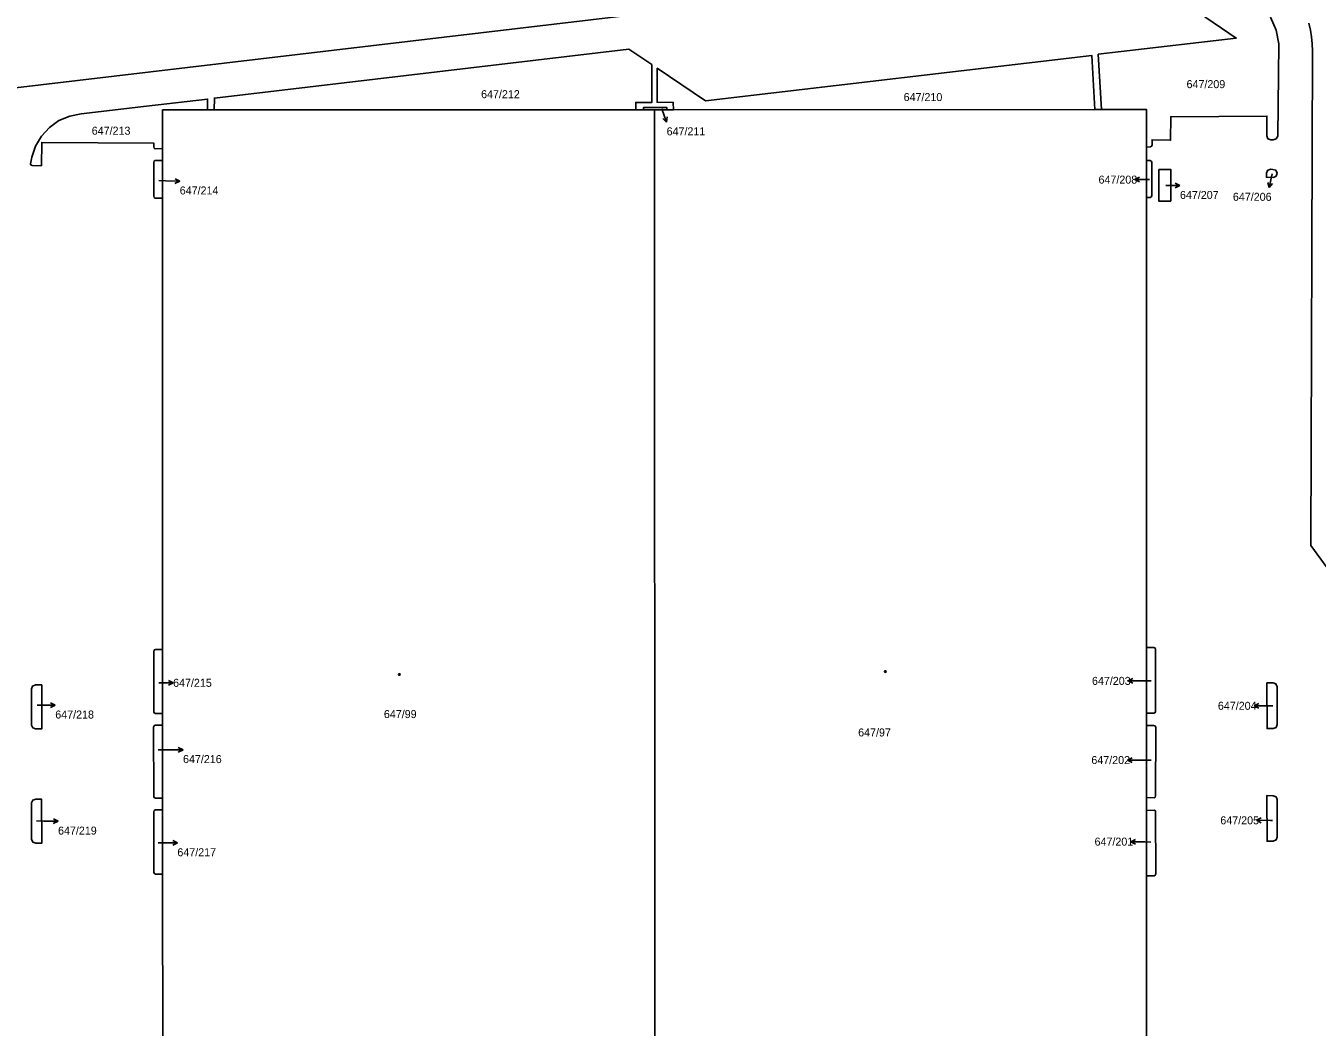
# Model space of a CAD drawing. Extents: x -724107 to -720612, y -1045267 to -1038441.
# Drawn here: x -722891.5 to -722617.2, y -1041657.4 to -1041444.7 of the extents above; entities that cross this region are included whole.
import ezdxf

# ---------------------------------------------------------------- set-up
doc = ezdxf.new("R2010")
doc.units = 0
for name, color, linetype in [('Hranice parcel', 7, 'Continuous'), ('Parcelní čísla', 7, 'Continuous'), ('Pop  PČ popisy', 7, 'Continuous'), ('Značky budov', 7, 'Continuous')]:
    doc.layers.add(name, color=color, linetype=linetype)

msp = doc.modelspace()

# ---------------------------------------------------------------- linework, layer by layer
at = {"layer": 'Hranice parcel'}
for p, q in [((-722851.47, -1041462.53), (-722852.91, -1041462.53)), ((-722761.96, -1041462.5), (-722851.47, -1041462.53)), ((-722760.31, -1041462.5), (-722761.96, -1041462.5)), ((-722757.93, -1041462.5), (-722760.31, -1041462.5)), ((-722757.93, -1041462.5), (-722757.91, -1041757.48)), ((-722755.37, -1041462.5), (-722757.93, -1041462.5)), ((-722753.96, -1041462.5), (-722755.37, -1041462.5)), ((-722664.39, -1041462.46), (-722753.96, -1041462.5)), ((-722663, -1041462.46), (-722664.39, -1041462.46)), ((-722862.46, -1041470.71), (-722862.46, -1041473.28)), ((-722653.43, -1041473.31), (-722653.43, -1041470.44)), ((-722862.46, -1041473.28), (-722862.46, -1041481.25)), ((-722653.43, -1041481.14), (-722653.43, -1041473.31)), ((-722862.46, -1041481.25), (-722862.45, -1041577.13)), ((-722653.42, -1041576.75), (-722653.43, -1041481.14)), ((-722862.45, -1041577.13), (-722862.45, -1041590.75)), ((-722653.42, -1041590.7), (-722653.42, -1041576.75)), ((-722862.45, -1041590.75), (-722862.45, -1041593.25)), ((-722653.42, -1041593.34), (-722653.42, -1041590.7)), ((-722862.45, -1041593.25), (-722862.45, -1041608.73)), ((-722653.42, -1041608.63), (-722653.42, -1041593.34)), ((-722862.45, -1041608.73), (-722862.45, -1041611.24)), ((-722653.42, -1041611.36), (-722653.42, -1041608.63)), ((-722862.45, -1041611.24), (-722862.45, -1041624.86)), ((-722653.42, -1041625.24), (-722653.42, -1041611.36)), ((-722862.45, -1041624.86), (-722862.43, -1041739.13)), ((-722653.41, -1041739.26), (-722653.42, -1041625.24))]:
    msp.add_line(p, q, dxfattribs=at)
for points in [[(-723065.73, -1041477.97), (-722911.77, -1041459.96), (-722763.68, -1041442.46), (-722640.12, -1041427.88)], [(-722663, -1041462.46), (-722663.7, -1041450.72), (-722634.39, -1041447.26), (-722650.43, -1041436.3)], [(-722627.08, -1041442.84), (-722625.91, -1041445.59), (-722625.34, -1041448.51), (-722625.58, -1041468.11), (-722625.92, -1041468.69), (-722626.54, -1041468.9), (-722627.05, -1041468.9), (-722627.67, -1041468.67), (-722627.9, -1041468.07), (-722627.87, -1041463.84), (-722648.31, -1041463.98), (-722648.32, -1041468.98), (-722652.26, -1041468.87), (-722652.26, -1041469.99), (-722652.37, -1041470.25), (-722652.59, -1041470.37), (-722653.43, -1041470.44)], [(-722618.95, -1041444.12), (-722618.61, -1041445.57), (-722618.36, -1041447.03), (-722618.22, -1041448.51), (-722618.18, -1041449.99)], [(-722851.47, -1041462.53), (-722851.46, -1041460.03), (-722763.39, -1041449.65), (-722758.54, -1041452.91), (-722758.52, -1041460.95), (-722761.93, -1041460.94), (-722761.96, -1041462.5)], [(-722753.96, -1041462.5), (-722753.98, -1041460.93), (-722757.41, -1041460.91), (-722757.39, -1041453.69), (-722747.11, -1041460.6), (-722665.06, -1041450.95), (-722664.39, -1041462.46)], [(-722618.18, -1041449.99), (-722618.53, -1041555.06), (-722615.08, -1041559.79), (-722614.93, -1041733.5), (-722618.38, -1041738.26), (-722618.4, -1041745.25)], [(-722862.46, -1041470.71), (-722864.02, -1041470.77), (-722864.25, -1041470.63), (-722864.33, -1041470.37), (-722864.34, -1041469.59), (-722888.12, -1041469.44), (-722888.21, -1041474.39), (-722890.18, -1041474.36), (-722890.42, -1041474.23), (-722890.52, -1041474.01), (-722890.22, -1041472.59), (-722889.47, -1041470.23), (-722888.21, -1041468.1), (-722886.5, -1041466.26), (-722884.48, -1041464.81), (-722882.17, -1041463.86), (-722879.75, -1041463.38), (-722865.85, -1041461.76), (-722852.92, -1041460.23), (-722852.91, -1041462.53)], [(-722852.91, -1041462.53), (-722862.46, -1041462.53), (-722862.46, -1041470.71)], [(-722760.31, -1041462.5), (-722760.33, -1041462.05), (-722755.37, -1041462.01), (-722755.37, -1041462.5)], [(-722653.43, -1041470.44), (-722653.43, -1041462.46), (-722663, -1041462.46)], [(-722862.46, -1041481.25), (-722864.01, -1041481.28), (-722864.27, -1041481.12), (-722864.34, -1041480.88), (-722864.34, -1041473.68), (-722864.26, -1041473.41), (-722864.01, -1041473.29), (-722862.46, -1041473.28)], [(-722653.43, -1041473.31), (-722652.68, -1041473.3), (-722652.44, -1041473.4), (-722652.32, -1041473.65), (-722652.31, -1041480.79), (-722652.43, -1041481.01), (-722652.69, -1041481.12), (-722653.43, -1041481.14)], [(-722650.82, -1041475.19), (-722648.31, -1041475.18), (-722648.29, -1041481.9), (-722650.85, -1041481.89), (-722650.82, -1041475.19)], [(-722625.68, -1041475.96), (-722625.93, -1041476.58), (-722626.49, -1041476.87), (-722627.96, -1041476.84), (-722627.93, -1041475.98), (-722627.71, -1041475.38), (-722627.1, -1041475.15), (-722626.61, -1041475.16), (-722625.95, -1041475.34), (-722625.68, -1041475.96)], [(-722862.45, -1041590.75), (-722863.99, -1041590.74), (-722864.22, -1041590.65), (-722864.34, -1041590.4), (-722864.32, -1041577.49), (-722864.2, -1041577.25), (-722863.96, -1041577.14), (-722862.45, -1041577.13)], [(-722653.42, -1041576.75), (-722651.86, -1041576.73), (-722651.65, -1041576.82), (-722651.52, -1041577.1), (-722651.52, -1041590.32), (-722651.61, -1041590.56), (-722651.86, -1041590.69), (-722653.42, -1041590.7)], [(-722890.05, -1041593.8), (-722890.34, -1041593.22), (-722890.29, -1041585.55), (-722890.07, -1041584.95), (-722889.46, -1041584.67), (-722888.14, -1041584.69), (-722888.14, -1041594.03), (-722889.44, -1041594.02), (-722890.05, -1041593.8)], [(-722627.86, -1041584.22), (-722626.55, -1041584.23), (-722625.94, -1041584.47), (-722625.68, -1041585.08), (-722625.68, -1041593.1), (-722625.93, -1041593.71), (-722626.53, -1041593.96), (-722627.82, -1041593.98), (-722627.86, -1041584.22)], [(-722862.45, -1041608.73), (-722863.99, -1041608.77), (-722864.26, -1041608.63), (-722864.35, -1041608.39), (-722864.36, -1041593.63), (-722864.27, -1041593.37), (-722864.01, -1041593.25), (-722862.45, -1041593.25)], [(-722653.42, -1041593.34), (-722651.86, -1041593.34), (-722651.63, -1041593.41), (-722651.49, -1041593.71), (-722651.53, -1041608.27), (-722651.63, -1041608.54), (-722651.85, -1041608.65), (-722653.42, -1041608.63)], [(-722625.66, -1041609.05), (-722625.68, -1041617.05), (-722625.89, -1041617.63), (-722626.52, -1041617.87), (-722627.84, -1041617.89), (-722627.85, -1041608.16), (-722626.54, -1041608.22), (-722625.91, -1041608.43), (-722625.66, -1041609.05)], [(-722890.32, -1041609.75), (-722890.01, -1041609.15), (-722889.41, -1041608.95), (-722888.17, -1041608.96), (-722888.11, -1041618.29), (-722889.39, -1041618.3), (-722890.02, -1041618.11), (-722890.28, -1041617.47), (-722890.32, -1041609.75)], [(-722862.45, -1041624.86), (-722863.98, -1041624.87), (-722864.21, -1041624.77), (-722864.33, -1041624.51), (-722864.35, -1041611.62), (-722864.26, -1041611.4), (-722864, -1041611.26), (-722862.45, -1041611.24)], [(-722653.42, -1041611.36), (-722651.83, -1041611.28), (-722651.57, -1041611.46), (-722651.5, -1041611.7), (-722651.49, -1041624.85), (-722651.59, -1041625.13), (-722651.84, -1041625.22), (-722653.42, -1041625.24)]]:
    msp.add_lwpolyline(points, dxfattribs=at)
at = {"layer": 'Pop  PČ popisy'}
for p, q in [((-722756.43, -1041462.29), (-722755.4, -1041465.11)), ((-722755.4, -1041465.11), (-722756.22, -1041464.34)), ((-722755.4, -1041465.11), (-722755.28, -1041464)), ((-722626.73, -1041476.09), (-722627.41, -1041479.01)), ((-722863.26, -1041477.53), (-722861.82, -1041477.57)), ((-722861.82, -1041477.57), (-722858.82, -1041477.68)), ((-722858.82, -1041477.68), (-722859.84, -1041478.14)), ((-722858.82, -1041477.68), (-722859.8, -1041477.14)), ((-722655.96, -1041477.34), (-722654.96, -1041476.84)), ((-722652.96, -1041477.34), (-722655.96, -1041477.34)), ((-722655.96, -1041477.34), (-722654.96, -1041477.84)), ((-722652.96, -1041477.34), (-722652.84, -1041477.34)), ((-722649.34, -1041478.62), (-722646.34, -1041478.62)), ((-722646.34, -1041478.62), (-722647.34, -1041478.12)), ((-722646.34, -1041478.62), (-722647.34, -1041479.12)), ((-722627.41, -1041479.01), (-722627.67, -1041477.93)), ((-722627.41, -1041479.01), (-722626.69, -1041478.15)), ((-722657.35, -1041583.83), (-722656.35, -1041583.33)), ((-722863.23, -1041584.28), (-722860.23, -1041584.23)), ((-722860.23, -1041584.23), (-722861.24, -1041583.74)), ((-722860.23, -1041584.23), (-722861.22, -1041584.75)), ((-722654.35, -1041583.83), (-722657.35, -1041583.83)), ((-722657.35, -1041583.83), (-722656.35, -1041584.33)), ((-722654.35, -1041583.83), (-722652.49, -1041583.83)), ((-722885.26, -1041589), (-722886.26, -1041588.5)), ((-722630.6, -1041589.12), (-722629.6, -1041588.62)), ((-722888.26, -1041589), (-722889.1, -1041589)), ((-722888.26, -1041589), (-722885.26, -1041589)), ((-722885.26, -1041589), (-722886.26, -1041589.5)), ((-722627.6, -1041589.12), (-722630.6, -1041589.12)), ((-722630.6, -1041589.12), (-722629.6, -1041589.62)), ((-722627.6, -1041589.12), (-722626.58, -1041589.12)), ((-722861.12, -1041598.46), (-722863.41, -1041598.46)), ((-722861.12, -1041598.46), (-722858.12, -1041598.46)), ((-722858.12, -1041598.46), (-722859.12, -1041597.96)), ((-722858.12, -1041598.46), (-722859.12, -1041598.96)), ((-722657.48, -1041600.65), (-722656.48, -1041600.15)), ((-722654.48, -1041600.65), (-722657.48, -1041600.65)), ((-722657.48, -1041600.65), (-722656.48, -1041601.15)), ((-722654.48, -1041600.65), (-722652.45, -1041600.65)), ((-722889.28, -1041613.58), (-722887.67, -1041613.61)), ((-722887.67, -1041613.61), (-722884.67, -1041613.66)), ((-722884.67, -1041613.66), (-722885.68, -1041614.15)), ((-722884.67, -1041613.66), (-722885.66, -1041613.14)), ((-722630.08, -1041613.44), (-722629.07, -1041612.95)), ((-722627.08, -1041613.49), (-722630.08, -1041613.44)), ((-722630.08, -1041613.44), (-722629.09, -1041613.96)), ((-722627.08, -1041613.49), (-722626.67, -1041613.49)), ((-722862.32, -1041618.26), (-722863.41, -1041618.26)), ((-722862.32, -1041618.26), (-722859.32, -1041618.26)), ((-722859.32, -1041618.26), (-722860.32, -1041617.76)), ((-722859.32, -1041618.26), (-722860.32, -1041618.76)), ((-722656.8, -1041617.99), (-722655.79, -1041617.5)), ((-722653.8, -1041618.04), (-722656.8, -1041617.99)), ((-722656.8, -1041617.99), (-722655.81, -1041618.51)), ((-722652.53, -1041618.06), (-722653.8, -1041618.04))]:
    msp.add_line(p, q, dxfattribs=at)
at = {"layer": 'Značky budov'}
for centre in [(-722812.18, -1041582.46), (-722708.94, -1041581.85)]:
    msp.add_circle(centre, 0.175, dxfattribs=at)

# ---------------------------------------------------------------- texts
at = {"layer": 'Parcelní čísla'}
for s, p in [('647/209', (-722644.94, -1041457.91)), ('647/212', (-722794.8, -1041460.04)), ('647/210', (-722705.04, -1041460.65)), ('647/213', (-722877.51, -1041467.8)), ('647/211', (-722755.39, -1041467.93)), ('647/208', (-722663.64, -1041478.19)), ('647/214', (-722858.82, -1041480.49)), ('647/207', (-722646.34, -1041481.45)), ('647/206', (-722635.09, -1041481.84)), ('647/215', (-722860.23, -1041585.09)), ('647/203', (-722665.03, -1041584.68)), ('647/204', (-722638.28, -1041589.97)), ('647/218', (-722885.26, -1041591.83)), ('647/99', (-722815.45, -1041591.73)), ('647/97', (-722714.7, -1041595.63)), ('647/216', (-722858.12, -1041601.29)), ('647/202', (-722665.16, -1041601.5)), ('647/205', (-722637.76, -1041614.3)), ('647/219', (-722884.67, -1041616.49)), ('647/201', (-722664.48, -1041618.83)), ('647/217', (-722859.32, -1041621.09))]:
    msp.add_text(s, height=1.7, dxfattribs=at).set_placement(p)

doc.saveas('drawing.dxf')
